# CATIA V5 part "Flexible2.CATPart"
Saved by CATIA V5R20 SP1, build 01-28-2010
Part number: Flexible2
Bounding box of the stored display mesh (mm): x 68.825 to 83.825, y -49 to 7.079, z 0 to 6
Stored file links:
  F:\Pro\Emplois\1_Chercheur\ThinkMOTION\MMS\MMS_GR1\abruchon\Catia\Flexible2.CATPart
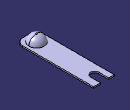
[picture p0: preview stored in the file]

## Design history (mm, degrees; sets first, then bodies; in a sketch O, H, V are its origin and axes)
Body1 (main body)
  Sketch1 on xy-plane, origin (0, 0, 0), H (1, 0, 0), V (0, 1, 0)
    line L1 (83.825, 7.079) -> (83.825, -49)
    line L2 (83.825, -49) -> (68.825, -49)
    line L3 (68.825, -49) -> (68.825, 7.079)
    line L4 (72.825, 7.079) -> (72.825, 0)
    point P6 (72.825, 0)
    line L5 (78.825, 7.079) -> (78.825, 0)
    point P8 (78.825, 0)
    arc A1 centre (75.825, 0) radius 3 from (72.825, 0) to (78.825, 0) ccw
    line L6 (78.825, 7.079) -> (83.825, 7.079)
    line L7 (72.825, 7.079) -> (68.825, 7.079)
    length L3 = 56.079
    radius A1 = 3
    distance L1 L3 = 15
    length L5 = 7.079
    length L4 = 7.079
    distance L4 L5 = 6
    distance L5 L1 = 5
    horizontal: L2 H, L6 H, L7 H
    vertical: L1 V, L3 V, L4 V, L5 V
    coincidence: P6 H, P8 H
  Pad1: profile Sketch1, direction (0, 0, 1), length 1
  Sketch2 on end face of Pad1, origin (0, 0, 1), H (1, 0, 0), V (0, 1, 0)
    circle A1 centre (76.325, -41.5) radius 5.5
    reference projected line E1 (68.825, -49) -> (83.825, -49) from edge [face of Pad1 from Sketch1.L2 | end face of Pad1]
    reference projected line E2 (68.825, 7.079) -> (68.825, -49) from edge [face of Pad1 from Sketch1.L3 | end face of Pad1]
    reference projected line E3 (83.825, -49) -> (83.825, 7.079) from edge [face of Pad1 from Sketch1.L1 | end face of Pad1]
    distance A1 E1 = 2
    distance E2 A1 = 2
    distance E3 A1 = 2
  Pad2: profile Sketch2, direction (0, 0, 1), length 5
  Fillet1: radius 5, on end face of Pad2
  Fillet2: radius 5, on edge [face of Pad1 from Sketch1.L1 | face of Pad1 from Sketch1.L2]
  Fillet3: radius 5, on edge [face of Pad1 from Sketch1.L2 | face of Pad1 from Sketch1.L3]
